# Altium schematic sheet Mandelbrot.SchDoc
size A; DocumentNumber: 1; SheetNumber: 1; SheetTotal: 1
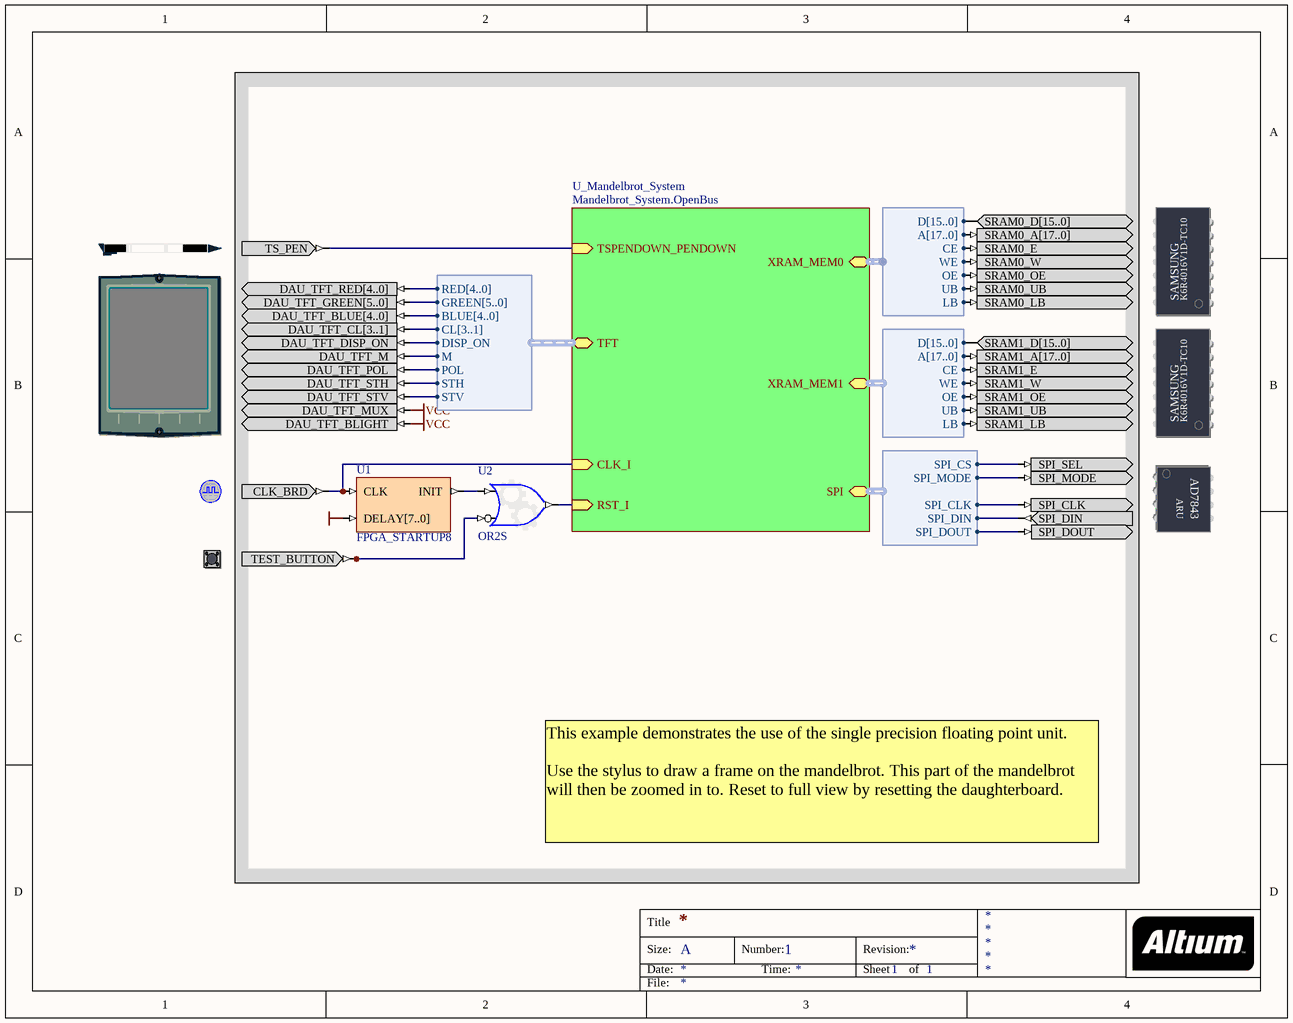
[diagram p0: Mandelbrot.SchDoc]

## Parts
(Parts that share a designator on the sheet are numbered #1, #2 ... from top to bottom, then left to right.)
?#1  SRAM_DAUGHTER0  (value not drawn)
?#2  TOUCHSCREEN_PEN_DOWN  (value not drawn)
?#3  TFT_LCD  (value not drawn)
?#4  SRAM_DAUGHTER1  (value not drawn)
?#5  CLOCK_BOARD  (value not drawn)
?#6  TEST_BUTTON  (value not drawn)
?#7  TOUCH_SCREEN_DIGITIZER  (value not drawn)
U1  FPGA_STARTUP8
U2  OR2S

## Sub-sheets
U_Mandelbrot_System = Mandelbrot_System.OpenBus: RST_I (in), CLK_I (in), XRAM_MEM1 (harness WB_MEM_CTRL_SRAM16_A18), XRAM_MEM0 (harness WB_MEM_CTRL_SRAM16_A18), TSPENDOWN_PENDOWN (in), SPI (harness SPI_W_NB), TFT (harness VGA32_TFT)

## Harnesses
WB_MEM_CTRL_SRAM16_A18: D[15..0], A[17..0], CE, WE, OE, UB, LB
VGA32_TFT: RED[4..0], GREEN[5..0], BLUE[4..0], CL[3..1], DISP_ON, M, POL, STH, STV
SPI_W_NB: SPI_DOUT, SPI_DIN, SPI_CLK, SPI_MODE, SPI_CS

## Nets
VCC: ?#3.DAU_TFT_BLIGHT ?#3.DAU_TFT_MUX
VCCBUS[..]: U1.DELAY[7..0]
Net?#1_SRAM0_E: ?#1.SRAM0_E ; sheet U_Mandelbrot_System/XRAM_MEM0.CE
Net?#1_SRAM0_LB: ?#1.SRAM0_LB ; sheet U_Mandelbrot_System/XRAM_MEM0.LB
Net?#1_SRAM0_OE: ?#1.SRAM0_OE ; sheet U_Mandelbrot_System/XRAM_MEM0.OE
Net?#1_SRAM0_UB: ?#1.SRAM0_UB ; sheet U_Mandelbrot_System/XRAM_MEM0.UB
Net?#1_SRAM0_W: ?#1.SRAM0_W ; sheet U_Mandelbrot_System/XRAM_MEM0.WE
Net?#2_TS_PEN: ?#2.TS_PEN ; sheet U_Mandelbrot_System/TSPENDOWN_PENDOWN
Net?#3_DAU_TFT_DISP_ON: ?#3.DAU_TFT_DISP_ON ; sheet U_Mandelbrot_System/TFT.DISP_ON
Net?#3_DAU_TFT_M: ?#3.DAU_TFT_M ; sheet U_Mandelbrot_System/TFT.M
Net?#3_DAU_TFT_POL: ?#3.DAU_TFT_POL ; sheet U_Mandelbrot_System/TFT.POL
Net?#3_DAU_TFT_STH: ?#3.DAU_TFT_STH ; sheet U_Mandelbrot_System/TFT.STH
Net?#3_DAU_TFT_STV: ?#3.DAU_TFT_STV ; sheet U_Mandelbrot_System/TFT.STV
Net?#4_SRAM1_E: ?#4.SRAM1_E ; sheet U_Mandelbrot_System/XRAM_MEM1.CE
Net?#4_SRAM1_LB: ?#4.SRAM1_LB ; sheet U_Mandelbrot_System/XRAM_MEM1.LB
Net?#4_SRAM1_OE: ?#4.SRAM1_OE ; sheet U_Mandelbrot_System/XRAM_MEM1.OE
Net?#4_SRAM1_UB: ?#4.SRAM1_UB ; sheet U_Mandelbrot_System/XRAM_MEM1.UB
Net?#4_SRAM1_W: ?#4.SRAM1_W ; sheet U_Mandelbrot_System/XRAM_MEM1.WE
Net?#5_CLK_BRD: ?#5.CLK_BRD U1.CLK ; sheet U_Mandelbrot_System/CLK_I
Net?#6_TEST_BUTTON: ?#6.TEST_BUTTON U2.I1
Net?#7_SPI_CLK: ?#7.SPI_CLK ; sheet U_Mandelbrot_System/SPI.SPI_CLK
Net?#7_SPI_DIN: ?#7.SPI_DIN ; sheet U_Mandelbrot_System/SPI.SPI_DIN
Net?#7_SPI_DOUT: ?#7.SPI_DOUT ; sheet U_Mandelbrot_System/SPI.SPI_DOUT
Net?#7_SPI_MODE: ?#7.SPI_MODE ; sheet U_Mandelbrot_System/SPI.SPI_MODE
Net?#7_SPI_SEL: ?#7.SPI_SEL ; sheet U_Mandelbrot_System/SPI.SPI_CS
NetU1_INIT: U1.INIT U2.I0
NetU2_O: U2.O ; sheet U_Mandelbrot_System/RST_I

Not connected (* = marked no-connect by the designer): ?#1 SRAM0_A[17..0] SRAM0_D[15..0]; ?#3 DAU_TFT_BLUE[4..0] DAU_TFT_CL[3..1] DAU_TFT_GREEN[5..0] DAU_TFT_RED[4..0]; ?#4 SRAM1_A[17..0] SRAM1_D[15..0]

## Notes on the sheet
- This example demonstrates the use of the single precision floating point unit.
  Use the stylus to draw a frame on the mandelbrot. This part of the mandelbrot will then be zoomed in to. Reset to full view by resetting the daughterboard.

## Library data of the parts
?#1 = SRAM_DAUGHTER0: Free Static RAM - Daughterboard; PortComponent: True
?#2 = TOUCH_SCREEN_PEN: TFT Touch Screen Pen; PortComponent: True
?#3 = TFT_LCD: TFT LCD Panel; PortComponent: True
?#4 = SRAM_DAUGHTER1: Free Static RAM - Daughterboard; PortComponent: True
?#5 = CLOCK_BOARD: Global System Clock Supply; PortComponent: True
?#6 = TEST_BUTTON: Test / Reset Button; PortComponent: True
?#7 = TOUCH_SCREEN_DIGITIZER: Touch Screen Digitizer; PortComponent: True
U1 = FPGA_STARTUP8: FPGA Startup With 8 Bit Delay
U2 = GATE: Configurable Generic Gate; ConfiguratorName: GENERIC_GATE; ConfigurationParameters: {}Version[1.0]{}GateKind[OR]{}BusInput[False]{}GateInputType[Bit]{}GateOutputOption[Normal]{}BusWidth[8]{}RegisterOutputs[False]{}NegativeClockEdge[False]{}InputCount[2]{}InputInvert0[False]{}InputInvert1[True]{}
